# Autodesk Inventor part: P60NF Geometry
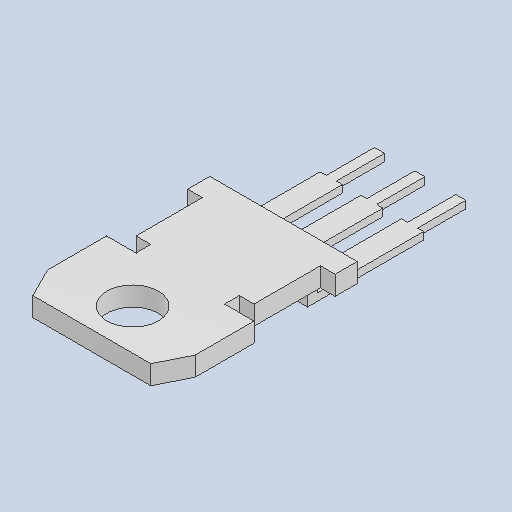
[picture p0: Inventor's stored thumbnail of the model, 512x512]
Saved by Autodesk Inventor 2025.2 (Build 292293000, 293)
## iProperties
Created: 2025-04
Part Number: P60NF Geometry
Material: Generic
Description: PART-P60NF Geometry-DESC
Document SubType Name: Modeling
Designer: BennF
Density: 1 g/cm^3
Appearance: Default
Author: BennF
Revision Number: NONE
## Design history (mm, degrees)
feature "Solid"
body "Solid1"
